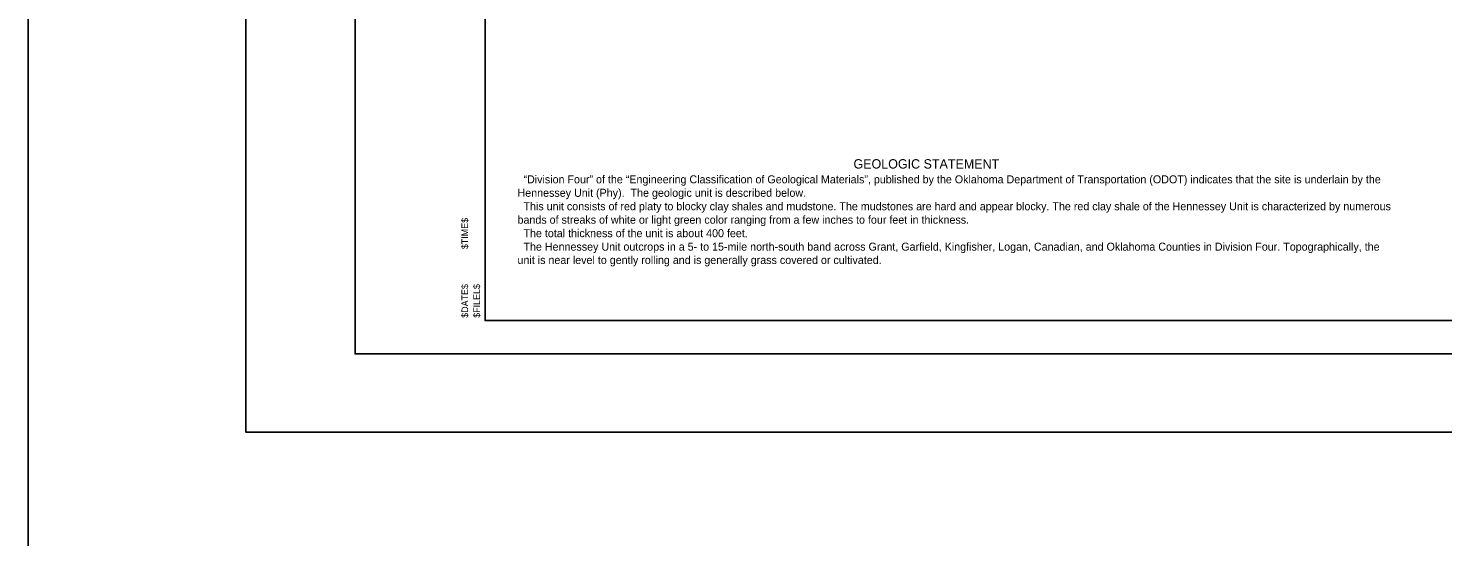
# Model space of a CAD drawing. Extents: x 2150161.5 to 2150203.1, y 143779.5 to 143868.5.
# Drawn here: x 2150161.53 to 2150182.73, y 143834.58 to 143842.21 of the extents above; entities that cross this region are included whole.
import ezdxf

# ---------------------------------------------------------------- set-up
doc = ezdxf.new("R2010")
doc.units = 0
for name, color, linetype in [('S', 7, 'Continuous'), ('SHT_Plot_Shape_Full', 7, 'Continuous'), ('SHT_Plot_Shape_Half', 7, 'Continuous'), ('SHT_Plot_Stamp', 7, 'Continuous'), ('SHT_Sheet_Border', 7, 'Continuous'), ('Text', 7, 'Continuous')]:
    doc.layers.add(name, color=color, linetype=linetype)

# ---------------------------------------------------------------- blocks, each defined once
blk = doc.blocks.new('Stamp_Plot_Stamp')
at = {"layer": 'SHT_Plot_Stamp'}
for s, p in [('$TIME$', (1.695, 1.572)), ('$DATE$', (1.695, 0.542)), ('$FILEL$', (1.873, 0.542))]:
    blk.add_text(s, height=0.1, rotation=90, dxfattribs=at).set_placement(p)

msp = doc.modelspace()

# ---------------------------------------------------------------- linework, layer by layer
at = {"layer": 'S'}
msp.add_lwpolyline([(2150161.53, 143868.477), (2150203.071, 143868.477), (2150203.071, 143779.536), (2150161.53, 143779.536)], close=True, dxfattribs=at)
at = {"layer": 'SHT_Plot_Shape_Full'}
msp.add_lwpolyline([(2150164.792, 143860.145), (2150200.792, 143860.145), (2150200.792, 143836.145), (2150164.792, 143836.145)], close=True, dxfattribs=at)
at = {"layer": 'SHT_Plot_Shape_Half'}
msp.add_lwpolyline([(2150166.429, 143859.32), (2150200.429, 143859.32), (2150200.429, 143837.32), (2150166.429, 143837.32)], close=True, dxfattribs=at)
at = {"layer": 'SHT_Sheet_Border'}
msp.add_lwpolyline([(2150199.879, 143837.82), (2150168.379, 143837.82), (2150168.379, 143858.82), (2150199.879, 143858.82)], close=True, dxfattribs=at)

# ---------------------------------------------------------------- block references
at = {"layer": 'SHT_Plot_Stamp'}
msp.add_blockref('Stamp_Plot_Stamp', (2150166.429, 143837.32), dxfattribs=at)

# ---------------------------------------------------------------- texts
at = {"layer": 'Text'}
for s, height, p in [('GEOLOGIC STATEMENT', 0.14, (2150173.901, 143840.101)), ('  “Division Four” of the “Engineering Classification of Geological Materials”, published by the Oklahoma Department of Transportation (ODOT) indicates that the site is underlain by the ', 0.12, (2150168.864, 143839.879)), ('Hennessey Unit (Phy).  The geologic unit is described below. ', 0.12, (2150168.864, 143839.677)), ('  This unit consists of red platy to blocky clay shales and mudstone. The mudstones are hard and appear blocky. The red clay shale of the Hennessey Unit is characterized by numerous ', 0.12, (2150168.864, 143839.475)), ('bands of streaks of white or light green color ranging from a few inches to four feet in thickness. ', 0.12, (2150168.864, 143839.273)), ('  The total thickness of the unit is about 400 feet.', 0.12, (2150168.864, 143839.071)), ('  The Hennessey Unit outcrops in a 5- to 15-mile north-south band across Grant, Garfield, Kingfisher, Logan, Canadian, and Oklahoma Counties in Division Four. Topographically, the ', 0.12, (2150168.864, 143838.869)), ('unit is near level to gently rolling and is generally grass covered or cultivated.', 0.12, (2150168.864, 143838.669))]:
    msp.add_text(s, height=height, dxfattribs=at).set_placement(p)

doc.saveas('drawing.dxf')
